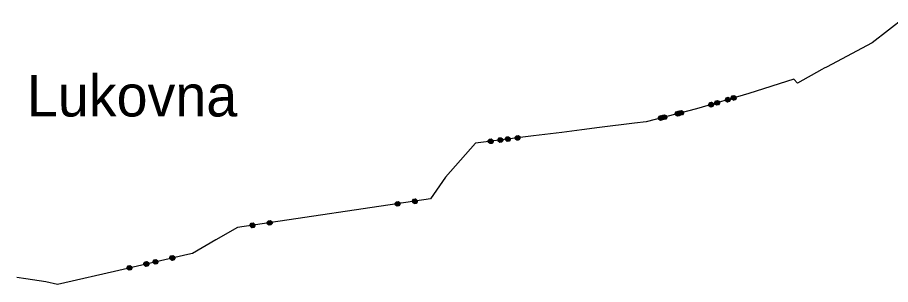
# Model space of a CAD drawing. Extents: x -643242 to -638517, y -1061413 to -1055378.
# Drawn here: x -641673 to -640917, y -1057253 to -1057022 of the extents above; entities that cross this region are included whole.
import ezdxf

# ---------------------------------------------------------------- set-up
doc = ezdxf.new("R2010")
doc.units = 0
doc.layers.add('HRA_KU', color=7, linetype='Continuous')
doc.layers.add('KU_OST', color=7, linetype='Continuous')

msp = doc.modelspace()

# ---------------------------------------------------------------- linework, layer by layer
at = {"layer": 'HRA_KU'}
for points in [[(-640904.71, -1057021.92), (-640932.96, -1057043.85), (-640972.67, -1057064.85), (-640974.62, -1057065.88), (-640976.75, -1057067.06), (-640997.8, -1057078.69), (-641000.71, -1057075.33), (-641039.66, -1057087.65), (-641085.07, -1057101.18), (-641128.71, -1057112.24), (-641138.67, -1057113.49), (-641169.16, -1057117.33), (-641184.32, -1057119.23), (-641201.64, -1057121.41), (-641226.25, -1057124.5), (-641276.33, -1057130.8), (-641302.26, -1057160.2), (-641315.28, -1057179.1), (-641482.43, -1057203.87), (-641501.07, -1057214.56), (-641521.41, -1057226.23), (-641525.24, -1057227.11), (-641588.69, -1057241.78), (-641631.8, -1057251.74), (-641638.09, -1057253.19), (-641648.11, -1057250.7), (-641665.45, -1057248.25), (-641673.32, -1057247.13)], [(-641067.46, -1057097.94), (-641068.88, -1057097.17), (-641069.34, -1057095.62), (-641068.57, -1057094.2), (-641067.02, -1057093.74), (-641065.6, -1057094.5), (-641065.14, -1057096.05), (-641065.91, -1057097.47), (-641067.46, -1057097.94), (-641067.36, -1057097.65), (-641065.98, -1057097.24), (-641065.65, -1057096.65), (-641067.95, -1057097.33), (-641068.55, -1057097.01), (-641065.33, -1057096.05), (-641065.47, -1057095.59), (-641068.69, -1057096.55), (-641068.82, -1057096.09), (-641065.6, -1057095.13), (-641065.74, -1057094.67), (-641068.96, -1057095.63), (-641068.64, -1057095.03), (-641066.34, -1057094.35), (-641066.94, -1057094.02), (-641068.32, -1057094.43)], [(-641058.24, -1057095.19), (-641059.66, -1057094.42), (-641060.12, -1057092.87), (-641059.36, -1057091.45), (-641057.8, -1057090.99), (-641056.39, -1057091.76), (-641055.92, -1057093.31), (-641056.69, -1057094.73), (-641058.24, -1057095.19), (-641058.25, -1057094.94), (-641056.87, -1057094.53), (-641056.55, -1057093.94), (-641058.85, -1057094.62), (-641059.45, -1057094.3), (-641056.23, -1057093.34), (-641056.37, -1057092.88), (-641059.59, -1057093.84), (-641059.72, -1057093.38), (-641056.5, -1057092.42), (-641056.64, -1057091.96), (-641059.86, -1057092.92), (-641059.54, -1057092.32), (-641057.24, -1057091.64), (-641057.83, -1057091.31), (-641059.21, -1057091.72)], [(-641053.08, -1057093.65), (-641054.5, -1057092.89), (-641054.96, -1057091.33), (-641054.2, -1057089.92), (-641052.65, -1057089.45), (-641051.23, -1057090.22), (-641050.76, -1057091.77), (-641051.53, -1057093.19), (-641053.08, -1057093.65), (-641053.1, -1057093.41), (-641051.72, -1057093), (-641051.39, -1057092.4), (-641053.69, -1057093.08), (-641054.29, -1057092.76), (-641051.07, -1057091.8), (-641051.21, -1057091.34), (-641054.43, -1057092.3), (-641054.56, -1057091.84), (-641051.34, -1057090.88), (-641051.48, -1057090.42), (-641054.7, -1057091.38), (-641054.38, -1057090.78), (-641052.08, -1057090.1), (-641052.67, -1057089.78), (-641054.05, -1057090.19)], [(-641098.73, -1057106.62), (-641100.12, -1057105.8), (-641100.52, -1057104.23), (-641099.69, -1057102.84), (-641098.12, -1057102.44), (-641096.73, -1057103.27), (-641096.34, -1057104.84), (-641097.16, -1057106.22), (-641098.73, -1057106.62), (-641098.73, -1057106.37), (-641097.34, -1057106.02), (-641096.99, -1057105.44), (-641099.32, -1057106.03), (-641099.9, -1057105.68), (-641096.64, -1057104.85), (-641096.76, -1057104.39), (-641100.02, -1057105.21), (-641100.13, -1057104.75), (-641096.88, -1057103.92), (-641097, -1057103.46), (-641100.25, -1057104.28), (-641099.91, -1057103.7), (-641097.58, -1057103.11), (-641098.16, -1057102.76), (-641099.56, -1057103.12)], [(-641072.62, -1057099.47), (-641074.04, -1057098.71), (-641074.5, -1057097.15), (-641073.73, -1057095.73), (-641072.18, -1057095.27), (-641070.76, -1057096.04), (-641070.3, -1057097.59), (-641071.07, -1057099.01), (-641072.62, -1057099.47), (-641072.52, -1057099.19), (-641071.14, -1057098.78), (-641070.81, -1057098.18), (-641073.11, -1057098.87), (-641073.71, -1057098.54), (-641070.49, -1057097.59), (-641070.63, -1057097.13), (-641073.85, -1057098.08), (-641073.98, -1057097.62), (-641070.76, -1057096.67), (-641070.9, -1057096.21), (-641074.12, -1057097.16), (-641073.8, -1057096.57), (-641071.5, -1057095.88), (-641072.09, -1057095.56), (-641073.47, -1057095.97)], [(-641116.2, -1057111.05), (-641117.58, -1057110.23), (-641117.98, -1057108.66), (-641117.16, -1057107.27), (-641115.59, -1057106.87), (-641114.2, -1057107.7), (-641113.8, -1057109.27), (-641114.63, -1057110.65), (-641116.2, -1057111.05), (-641116.08, -1057110.77), (-641114.69, -1057110.42), (-641114.34, -1057109.84), (-641116.67, -1057110.43), (-641117.25, -1057110.08), (-641113.99, -1057109.25), (-641114.11, -1057108.79), (-641117.37, -1057109.61), (-641117.49, -1057109.15), (-641114.23, -1057108.32), (-641114.35, -1057107.86), (-641117.6, -1057108.68), (-641117.26, -1057108.1), (-641114.93, -1057107.51), (-641115.51, -1057107.16), (-641116.91, -1057107.52)], [(-641113.27, -1057110.31), (-641114.66, -1057109.48), (-641115.05, -1057107.91), (-641114.23, -1057106.53), (-641112.66, -1057106.13), (-641111.27, -1057106.96), (-641110.88, -1057108.53), (-641111.7, -1057109.91), (-641113.27, -1057110.31), (-641113.16, -1057110.03), (-641111.76, -1057109.68), (-641111.41, -1057109.1), (-641113.74, -1057109.69), (-641114.32, -1057109.34), (-641111.07, -1057108.51), (-641111.18, -1057108.05), (-641114.44, -1057108.87), (-641114.56, -1057108.41), (-641111.3, -1057107.58), (-641111.42, -1057107.12), (-641114.68, -1057107.94), (-641114.33, -1057107.36), (-641112, -1057106.77), (-641112.59, -1057106.42), (-641113.98, -1057106.78)], [(-641101.66, -1057107.36), (-641103.04, -1057106.54), (-641103.44, -1057104.97), (-641102.62, -1057103.58), (-641101.05, -1057103.18), (-641099.66, -1057104.01), (-641099.26, -1057105.58), (-641100.09, -1057106.97), (-641101.66, -1057107.36), (-641101.66, -1057107.12), (-641100.26, -1057106.76), (-641099.92, -1057106.18), (-641102.24, -1057106.77), (-641102.83, -1057106.42), (-641099.57, -1057105.6), (-641099.69, -1057105.13), (-641102.94, -1057105.96), (-641103.06, -1057105.49), (-641099.81, -1057104.67), (-641099.92, -1057104.2), (-641103.18, -1057105.03), (-641102.83, -1057104.44), (-641100.51, -1057103.85), (-641101.09, -1057103.51), (-641102.49, -1057103.86)], [(-641248.88, -1057129.28), (-641250.16, -1057128.29), (-641250.36, -1057126.69), (-641249.37, -1057125.41), (-641247.77, -1057125.21), (-641246.49, -1057126.2), (-641246.29, -1057127.8), (-641247.28, -1057129.08), (-641248.88, -1057129.28), (-641248.85, -1057129.04), (-641247.43, -1057128.86), (-641247.01, -1057128.32), (-641249.39, -1057128.62), (-641249.93, -1057128.2), (-641246.59, -1057127.78), (-641246.65, -1057127.31), (-641249.99, -1057127.73), (-641250.05, -1057127.25), (-641246.71, -1057126.83), (-641246.77, -1057126.35), (-641250.11, -1057126.77), (-641249.69, -1057126.24), (-641247.31, -1057125.94), (-641247.85, -1057125.52), (-641249.28, -1057125.7)], [(-641240.48, -1057128.22), (-641241.75, -1057127.23), (-641241.95, -1057125.63), (-641240.96, -1057124.35), (-641239.36, -1057124.15), (-641238.08, -1057125.14), (-641237.88, -1057126.75), (-641238.87, -1057128.02), (-641240.48, -1057128.22), (-641240.45, -1057127.98), (-641239.02, -1057127.8), (-641238.6, -1057127.26), (-641240.98, -1057127.56), (-641241.52, -1057127.15), (-641238.19, -1057126.72), (-641238.25, -1057126.25), (-641241.58, -1057126.67), (-641241.64, -1057126.19), (-641238.31, -1057125.77), (-641238.37, -1057125.3), (-641241.7, -1057125.72), (-641241.28, -1057125.18), (-641238.9, -1057124.88), (-641239.44, -1057124.46), (-641240.87, -1057124.64)], [(-641263.77, -1057131.16), (-641265.04, -1057130.17), (-641265.24, -1057128.56), (-641264.25, -1057127.29), (-641262.65, -1057127.08), (-641261.37, -1057128.07), (-641261.17, -1057129.68), (-641262.16, -1057130.95), (-641263.77, -1057131.16), (-641263.62, -1057130.9), (-641262.19, -1057130.72), (-641261.77, -1057130.18), (-641264.15, -1057130.48), (-641264.69, -1057130.06), (-641261.36, -1057129.64), (-641261.42, -1057129.17), (-641264.75, -1057129.59), (-641264.81, -1057129.11), (-641261.48, -1057128.69), (-641261.54, -1057128.22), (-641264.87, -1057128.64), (-641264.45, -1057128.1), (-641262.07, -1057127.8), (-641262.61, -1057127.38), (-641264.04, -1057127.56)], [(-641255.36, -1057130.1), (-641256.63, -1057129.11), (-641256.83, -1057127.5), (-641255.85, -1057126.23), (-641254.24, -1057126.03), (-641252.97, -1057127.02), (-641252.76, -1057128.62), (-641253.75, -1057129.9), (-641255.36, -1057130.1), (-641255.21, -1057129.84), (-641253.78, -1057129.66), (-641253.36, -1057129.12), (-641255.75, -1057129.42), (-641256.28, -1057129.01), (-641252.95, -1057128.59), (-641253.01, -1057128.11), (-641256.34, -1057128.53), (-641256.4, -1057128.05), (-641253.07, -1057127.63), (-641253.13, -1057127.16), (-641256.46, -1057127.58), (-641256.05, -1057127.04), (-641253.66, -1057126.74), (-641254.2, -1057126.32), (-641255.63, -1057126.5)], [(-641344.26, -1057185.34), (-641345.55, -1057184.38), (-641345.79, -1057182.78), (-641344.83, -1057181.48), (-641343.23, -1057181.24), (-641341.93, -1057182.2), (-641341.7, -1057183.8), (-641342.66, -1057185.1), (-641344.26, -1057185.34), (-641344.12, -1057185.07), (-641342.69, -1057184.86), (-641342.29, -1057184.32), (-641344.66, -1057184.67), (-641345.21, -1057184.27), (-641341.88, -1057183.77), (-641341.95, -1057183.3), (-641345.28, -1057183.79), (-641345.35, -1057183.32), (-641342.02, -1057182.82), (-641342.09, -1057182.35), (-641345.42, -1057182.84), (-641345.01, -1057182.3), (-641342.64, -1057181.94), (-641343.18, -1057181.54), (-641344.61, -1057181.75)], [(-641329.42, -1057183.13), (-641330.72, -1057182.17), (-641330.95, -1057180.57), (-641329.99, -1057179.28), (-641328.39, -1057179.04), (-641327.1, -1057180), (-641326.86, -1057181.6), (-641327.82, -1057182.9), (-641329.42, -1057183.13), (-641329.4, -1057182.89), (-641327.97, -1057182.68), (-641327.57, -1057182.13), (-641329.94, -1057182.48), (-641330.49, -1057182.08), (-641327.16, -1057181.59), (-641327.23, -1057181.11), (-641330.56, -1057181.61), (-641330.63, -1057181.13), (-641327.3, -1057180.64), (-641327.38, -1057180.16), (-641330.7, -1057180.66), (-641330.29, -1057180.11), (-641327.92, -1057179.76), (-641328.47, -1057179.35), (-641329.89, -1057179.56)], [(-641469.86, -1057203.95), (-641471.16, -1057202.99), (-641471.39, -1057201.39), (-641470.43, -1057200.09), (-641468.83, -1057199.86), (-641467.54, -1057200.82), (-641467.3, -1057202.42), (-641468.26, -1057203.71), (-641469.86, -1057203.95), (-641469.72, -1057203.69), (-641468.29, -1057203.48), (-641467.89, -1057202.93), (-641470.26, -1057203.28), (-641470.81, -1057202.88), (-641467.49, -1057202.39), (-641467.56, -1057201.91), (-641470.88, -1057202.4), (-641470.95, -1057201.93), (-641467.63, -1057201.44), (-641467.7, -1057200.96), (-641471.02, -1057201.45), (-641470.62, -1057200.91), (-641468.24, -1057200.56), (-641468.79, -1057200.15), (-641470.21, -1057200.36)], [(-641455.02, -1057201.75), (-641456.32, -1057200.79), (-641456.56, -1057199.19), (-641455.6, -1057197.89), (-641453.99, -1057197.65), (-641452.7, -1057198.61), (-641452.46, -1057200.21), (-641453.42, -1057201.51), (-641455.02, -1057201.75), (-641455, -1057201.5), (-641453.58, -1057201.29), (-641453.17, -1057200.74), (-641455.55, -1057201.1), (-641456.09, -1057200.69), (-641452.77, -1057200.2), (-641452.84, -1057199.72), (-641456.16, -1057200.22), (-641456.23, -1057199.74), (-641452.91, -1057199.25), (-641452.98, -1057198.78), (-641456.3, -1057199.27), (-641455.9, -1057198.72), (-641453.52, -1057198.37), (-641454.07, -1057197.97), (-641455.49, -1057198.18)], [(-641539.01, -1057232.26), (-641540.38, -1057231.41), (-641540.75, -1057229.83), (-641539.89, -1057228.46), (-641538.31, -1057228.1), (-641536.95, -1057228.95), (-641536.58, -1057230.53), (-641537.43, -1057231.9), (-641539.01, -1057232.26), (-641539.01, -1057232.02), (-641537.61, -1057231.69), (-641537.25, -1057231.12), (-641539.58, -1057231.66), (-641540.16, -1057231.3), (-641536.89, -1057230.54), (-641536.99, -1057230.07), (-641540.27, -1057230.83), (-641540.38, -1057230.36), (-641537.1, -1057229.6), (-641537.21, -1057229.14), (-641540.48, -1057229.89), (-641540.13, -1057229.32), (-641537.79, -1057228.78), (-641538.36, -1057228.42), (-641539.77, -1057228.74)], [(-641576.16, -1057240.85), (-641577.52, -1057240), (-641577.89, -1057238.42), (-641577.04, -1057237.05), (-641575.46, -1057236.69), (-641574.09, -1057237.54), (-641573.72, -1057239.12), (-641574.58, -1057240.49), (-641576.16, -1057240.85), (-641576.03, -1057240.58), (-641574.63, -1057240.26), (-641574.27, -1057239.68), (-641576.61, -1057240.22), (-641577.19, -1057239.86), (-641573.91, -1057239.1), (-641574.02, -1057238.64), (-641577.29, -1057239.39), (-641577.4, -1057238.93), (-641574.13, -1057238.17), (-641574.24, -1057237.7), (-641577.51, -1057238.46), (-641577.15, -1057237.88), (-641574.81, -1057237.34), (-641575.39, -1057236.98), (-641576.79, -1057237.31)], [(-641561.54, -1057237.47), (-641562.91, -1057236.62), (-641563.28, -1057235.04), (-641562.42, -1057233.67), (-641560.84, -1057233.31), (-641559.48, -1057234.16), (-641559.11, -1057235.74), (-641559.96, -1057237.11), (-641561.54, -1057237.47), (-641561.54, -1057237.23), (-641560.13, -1057236.9), (-641559.78, -1057236.32), (-641562.11, -1057236.87), (-641562.69, -1057236.51), (-641559.42, -1057235.75), (-641559.52, -1057235.28), (-641562.8, -1057236.04), (-641562.91, -1057235.57), (-641559.63, -1057234.81), (-641559.74, -1057234.35), (-641563.01, -1057235.1), (-641562.65, -1057234.53), (-641560.32, -1057233.99), (-641560.89, -1057233.63), (-641562.3, -1057233.95)], [(-641553.63, -1057235.65), (-641554.99, -1057234.79), (-641555.36, -1057233.21), (-641554.51, -1057231.85), (-641552.93, -1057231.48), (-641551.56, -1057232.33), (-641551.19, -1057233.91), (-641552.05, -1057235.28), (-641553.63, -1057235.65), (-641553.51, -1057235.37), (-641552.1, -1057235.05), (-641551.74, -1057234.47), (-641554.08, -1057235.01), (-641554.66, -1057234.65), (-641551.38, -1057233.89), (-641551.49, -1057233.43), (-641554.77, -1057234.18), (-641554.87, -1057233.72), (-641551.6, -1057232.96), (-641551.71, -1057232.49), (-641554.98, -1057233.25), (-641554.62, -1057232.67), (-641552.28, -1057232.13), (-641552.86, -1057231.77), (-641554.26, -1057232.1)]]:
    msp.add_lwpolyline(points, dxfattribs=at)

# ---------------------------------------------------------------- texts
at = {"layer": 'KU_OST'}
msp.add_text(' Lukovna', height=36, dxfattribs=at).set_placement((-641677.94, -1057107.66))

doc.saveas('drawing.dxf')
